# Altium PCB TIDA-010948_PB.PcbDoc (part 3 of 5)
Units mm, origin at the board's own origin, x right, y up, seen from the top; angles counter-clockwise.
Board outline 140 x 180 mm, 4 copper layers (Top Layer, Mid-Layer 1, Mid-Layer 2, Bottom Layer), stack 1.554 mm thick; 481 components, 274 nets, 1278 pads, 301 vias.
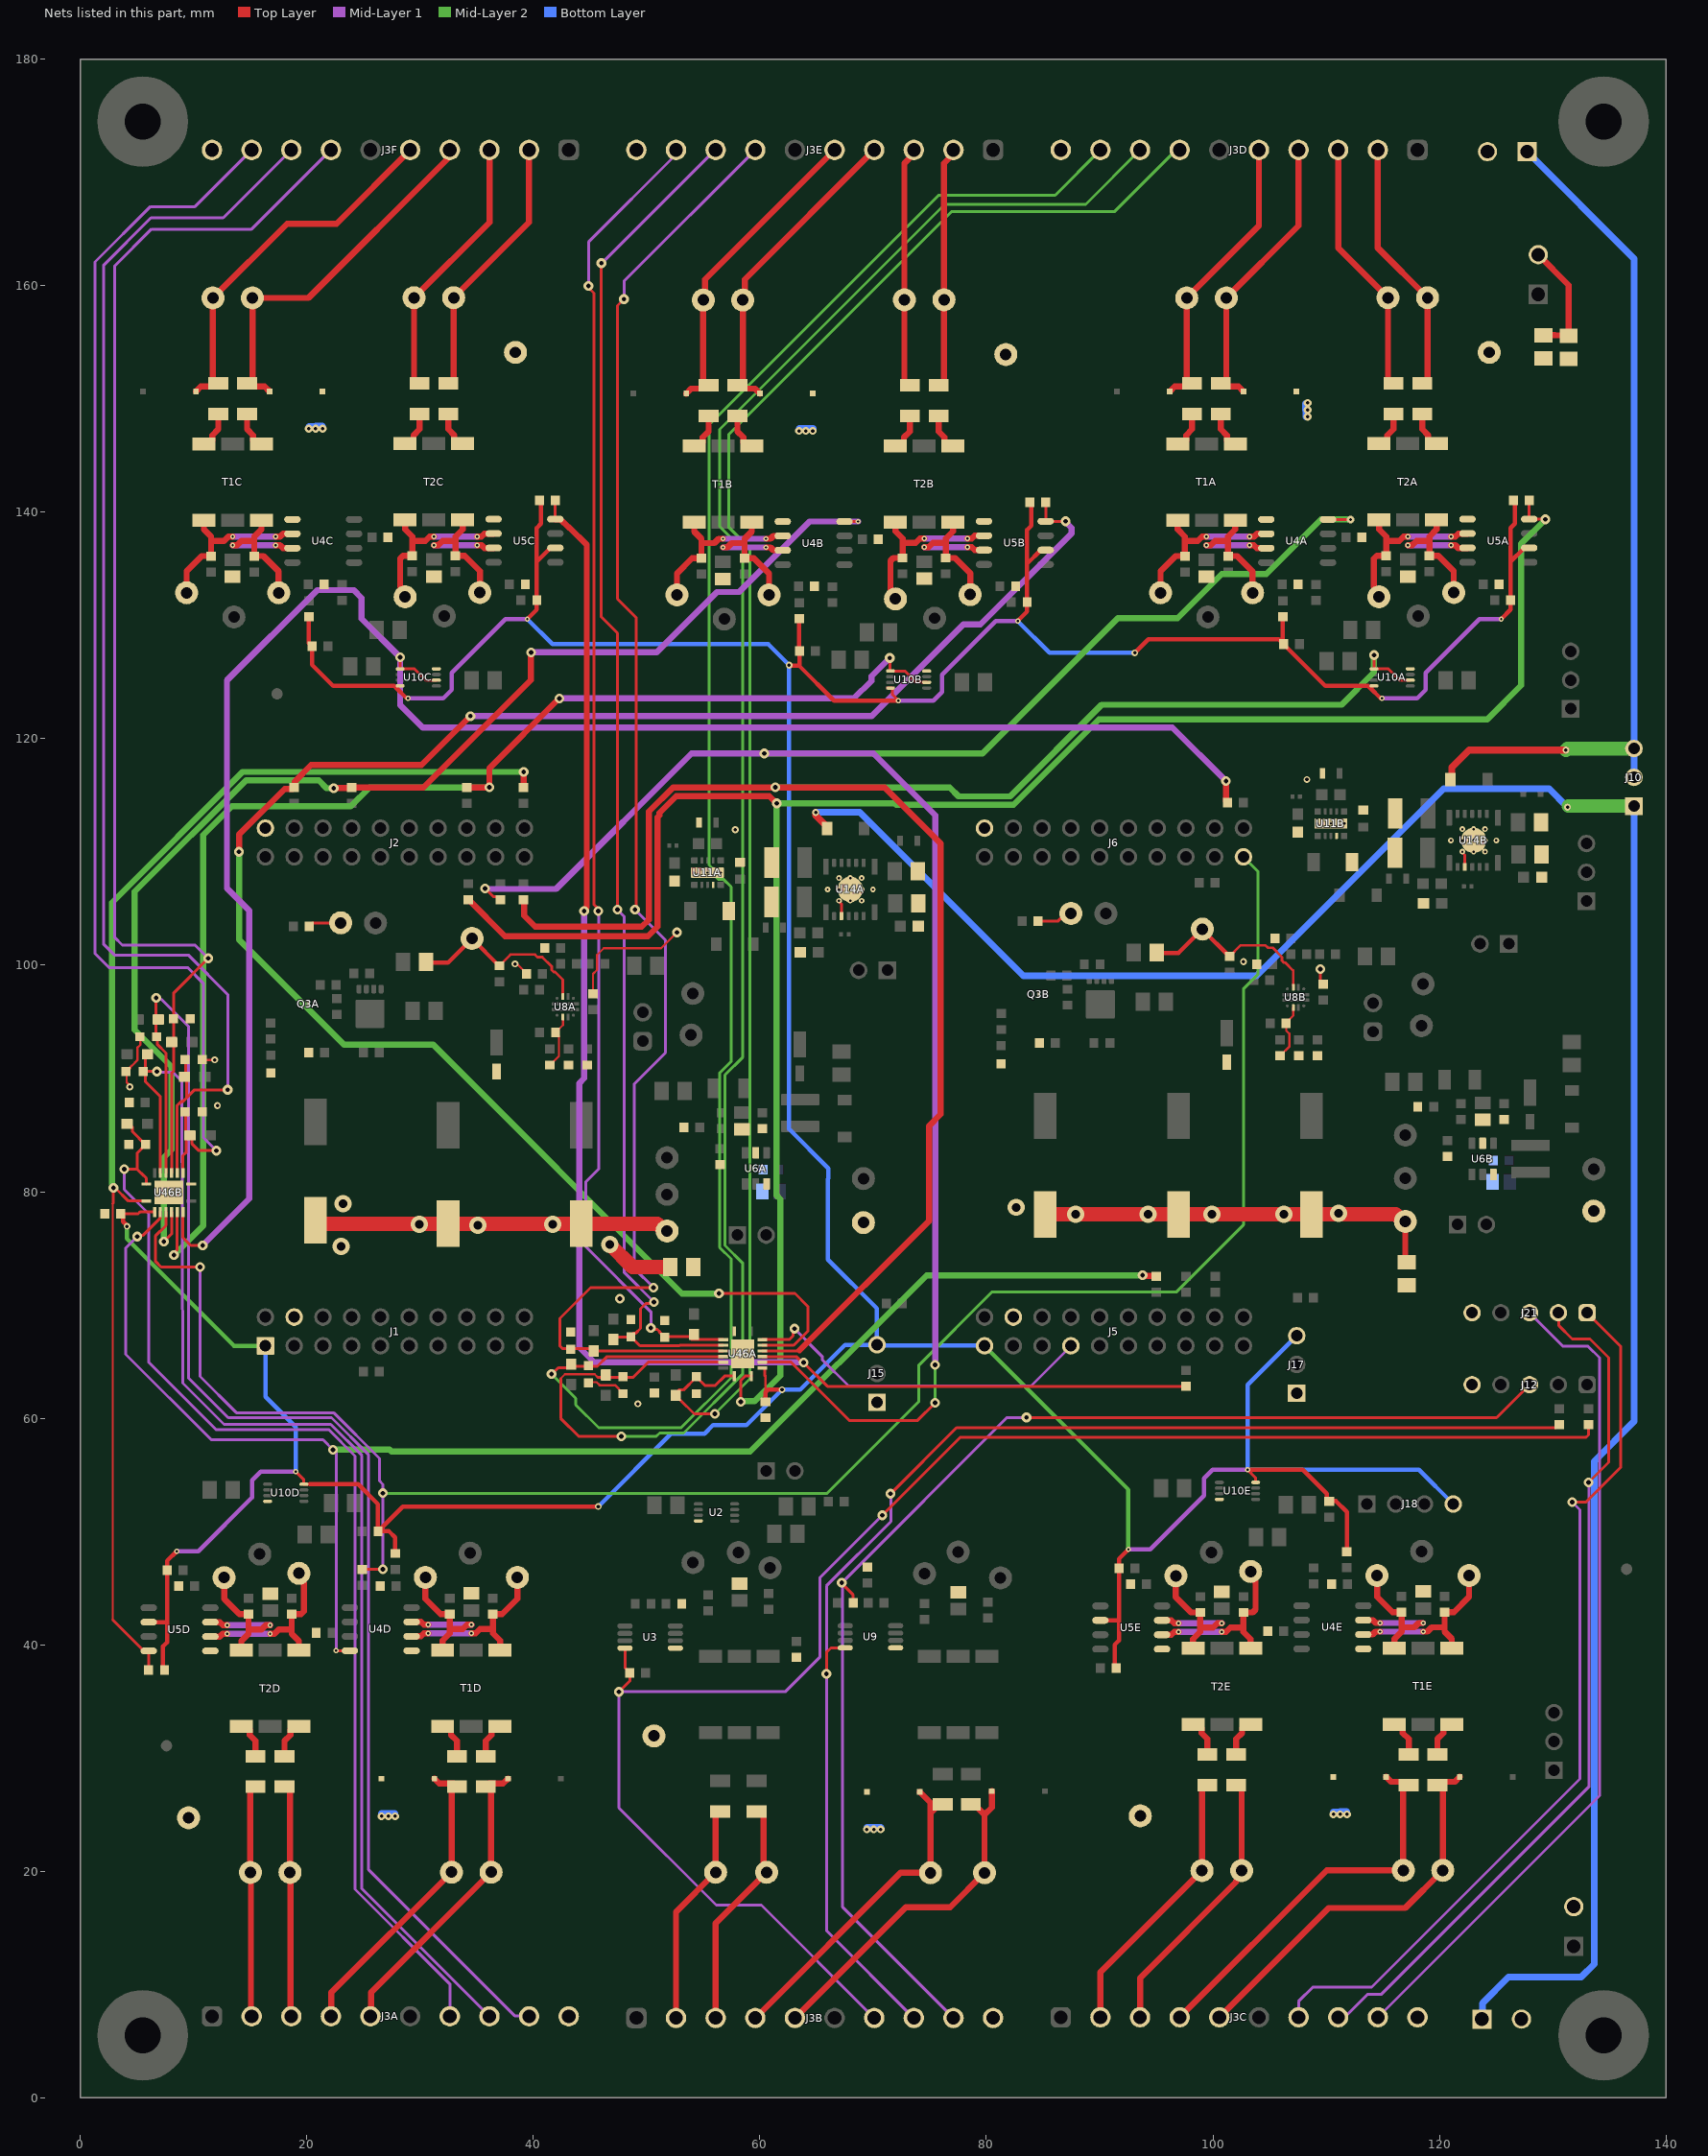
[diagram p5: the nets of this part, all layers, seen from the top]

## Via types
v1: diameter 0.457/0.457/0.457/0.457 (per signal layer), hole 0.203, Top Layer to Bottom Layer, tented both sides, 68 vias
v2: diameter 0.864, hole 0.406, Top Layer to Mid-Layer 1, 51 vias
v3: diameter 0.5, hole 0.2, Top Layer to Bottom Layer, 40 vias
v4: diameter 0.864, hole 0.406, Top Layer to Bottom Layer, 40 vias
v5: diameter 0.7, hole 0.3, Top Layer to Bottom Layer, 36 vias
v6: diameter 0.61, hole 0.3, Top Layer to Bottom Layer, 29 vias
v7: diameter 1.524, hole 0.762, Top Layer to Bottom Layer, tented both sides, 12 vias
v8: diameter 0.203, hole 0.203, Top Layer to Bottom Layer, tented both sides, 8 vias
v9: diameter 1.016, hole 0.508, Top Layer to Bottom Layer, tented both sides, 6 vias
v10: diameter 0.61, hole 0.3, Top Layer to Mid-Layer 1, 3 vias
v11: diameter 0.457, hole 0.203, Top Layer to Mid-Layer 1, tented both sides, 2 vias
v12: diameter 0.5, hole 0.2, Top Layer to Bottom Layer, tented both sides, 2 vias
v13: diameter 0.7, hole 0.203, Top Layer to Mid-Layer 1, tented both sides, 1 vias
v14: diameter 0.7, hole 0.254, Top Layer to Bottom Layer, 1 vias
v15: diameter 0.7, hole 0.254, Top Layer to Mid-Layer 1, 1 vias
v16: diameter 0.457/0.457 (per signal layer), hole 0.203, Top Layer to Mid-Layer 1, tented both sides, 1 vias

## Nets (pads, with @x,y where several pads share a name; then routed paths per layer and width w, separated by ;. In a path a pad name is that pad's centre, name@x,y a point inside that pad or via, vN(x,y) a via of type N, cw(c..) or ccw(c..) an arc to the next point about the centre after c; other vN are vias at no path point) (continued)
24V0_EXTERNAL_1: D6A.2 J10.1 J19.1 | length 204.1
  Top Layer w0.6: v6(64.92,113.497) 64.922,113.495 64.922,113.237 65.935,112.224 D6A.2@65.935,112.072
  Mid-Layer 2 w0.6: v6(131.311,113.96) 131.313,113.96 v6@131.407,114.054
  Mid-Layer 2 w1.2: v6@131.407,114.054 J10.1@137.181,114.054
  Bottom Layer w0.6: v6(64.92,113.497) 66.857,113.497 66.871,113.51 68.805,113.51 83.25,99.065 103.855,99.065 120.371,115.581 129.69,115.581 v6(131.311,113.96) ; J19.1@123.75,6.935 123.805,6.99 123.805,8.333 126.104,10.632 132.519,10.632 133.669,11.783 133.669,56.19 137.181,59.702 J10.1@137.181,114.054
24V0_EXTERNAL_2: D6B.2 J10.2 J10.3 J20.1 | length 77.1
  Top Layer w0.6: D6B.2@120.981,116.399 121.105,116.522 121.105,117.479 122.625,118.999 v6(131.175,118.999)
  Mid-Layer 2 w1.2: v6(131.175,118.999) 131.311,119.134 J10.3@137.181,119.134
  Bottom Layer w0.6: J20.1@127.75,171.85 137.181,162.419 J10.3@137.181,119.134 J10.2@137.181,116.594
BULK_RDYA: NT9A.1 R36A.2 TP34A.1 U8A.3 | length 16.9
  Top Layer w0.229: R36A.2@36.987,99.955 37.973,100.94 40.14,100.94 40.357,100.723 40.781,100.723 41.612,99.892 41.612,99.582 41.789,99.405 41.907,99.405 42.596,98.716 U8A.3@42.596,97.353
  Top Layer w0.381: NT9A.1@30.53,100.294 30.58,100.244 32.461,100.244 TP34A.1@34.58,102.363 34.58,102.337 36.962,99.955 R36A.2@36.987,99.955
BULK_RDYB: NT9B.1 R36B.2 TP34B.1 U8B.3 | length 16.9
  Top Layer w0.229: R36B.2@101.481,100.783 102.466,101.769 104.633,101.769 104.851,101.552 105.274,101.552 106.106,100.72 106.106,100.41 106.282,100.233 106.4,100.233 107.089,99.545 U8B.3@107.089,98.182
  Top Layer w0.381: NT9B.1@95.023,101.123 95.073,101.073 96.955,101.073 TP34B.1@99.074,103.192 99.074,103.165 101.456,100.783 R36B.2@101.481,100.783
CLKA_N: C15D.1 J3A.2 TP26D.1 | length 20.6
  Top Layer w0.54: J3A.2@15.115,7.181 15.058,7.239 15.058,19.83 TP26D.1@15,19.887 15,27.167 15.28,27.448 C15D.1@15.469,27.448
CLKA_P: C14D.1 J3A.3 TP25D.1 | length 20.6
  Top Layer w0.54: C14D.1@18.02,27.448 18.22,27.448 18.5,27.167 TP25D.1@18.5,19.887 18.558,19.83 18.558,7.239 J3A.3@18.615,7.181
CLKB_N: C35.1 J3B.2 TP10.1 | length 19.9
  Top Layer w0.54: J3B.2@52.591,7.032 52.591,16.398 TP10.1@56.091,19.898 56.091,25 56.371,25.28 C35.1@56.488,25.28
CLKB_P: C34.1 J3B.3 TP7.1 | length 20.7
  Top Layer w0.54: J3B.3@56.091,7.032 56.091,15.395 TP7.1@60.594,19.898 60.314,20.177 60.314,25 60.034,25.28 C34.1@59.709,25.28
CLKC_N: C15E.1 J3C.2 TP26E.1 | length 24.5
  Top Layer w0.54: J3C.2@90.067,7.09 90.067,11.074 TP26E.1@99.042,20.05 99.042,27.33 99.322,27.61 C15E.1@99.511,27.61
CLKC_P: C14E.1 J3C.3 TP25E.1 | length 24.6
  Top Layer w0.54: J3C.3@93.567,7.09 93.567,10.567 102.045,19.045 102.045,19.149 102.542,19.646 102.542,27.33 102.262,27.61 C14E.1@102.062,27.61
CLKD_N: C15A.1 J3D.2 TP26A.1 | length 22.7
  Top Layer w0.54: J3D.2@114.567,172 114.567,163.341 TP26A.1@118.958,158.95 118.958,151.67 118.678,151.39 C15A.1@118.489,151.39
CLKD_P: C14A.1 J3D.3 TP25A.1 | length 22.7
  Top Layer w0.54: J3D.3@111.067,172 111.067,163.341 TP25A.1@115.458,158.95 115.458,151.67 115.738,151.39 C14A.1@115.938,151.39
CLKE_N: C15B.1 J3E.2 TP26B.1 | length 21.4
  Top Layer w0.54: C15B.1@75.79,151.203 75.978,151.203 76.258,151.483 TP26B.1@76.258,158.763 76.258,170.826 77.091,171.659 J3E.2@77.091,172
CLKE_P: C14B.1 J3E.3 TP25B.1 | length 21.5
  Top Layer w0.54: C14B.1@73.238,151.203 73.038,151.203 72.758,151.483 TP25B.1@72.758,158.763 72.758,170.826 73.591,171.659 J3E.3@73.591,172
CLKF_N: C15C.1 J3F.2 TP26C.1 | length 23.7
  Top Layer w0.54: C15C.1@32.489,151.39 32.678,151.39 32.958,151.67 TP26C.1@32.958,158.95 39.615,165.608 J3F.2@39.615,172
CLKF_P: C14C.1 J3F.3 TP25C.1 | length 23.7
  Top Layer w0.54: C14C.1@29.938,151.39 29.738,151.39 29.458,151.67 TP25C.1@29.458,158.95 36.115,165.608 J3F.3@36.115,172
DA1A_N: R24A.2 T1A.3 TP17A.1 U4A.7 | length 18.7
  Top Layer w0.54: v1(99.44,137.086) 99.821,137.086 100.202,137.467 101.345,137.467 ; R24A.2@101.344,136.135 102.148,136.135 103.504,134.779 TP17A.1@103.503,132.895 ; v1(103.25,137.086) 103.631,137.086 103.885,136.832 U4A.7@104.716,136.832 ; 101.345,137.467 101.345,137.848 ; 101.345,137.467 101.345,137.848 ; 101.345,137.467 101.345,136.235 101.345,137.467 ; 101.345,137.848 101.98,138.483 ; 101.345,137.848 101.98,138.483 ; 101.98,138.483 T1A.3@101.979,139.308 101.98,138.483
  Mid-Layer 1 w0.54: v1(99.44,137.086) v1(103.25,137.086)
DA1A_P: R22A.2 T1A.1 TP16A.1 U4A.6 | length 15.4
  Top Layer w0.54: TP16A.1@95.375,132.895 95.376,134.792 96.718,136.135 R22A.2@97.534,136.135 ; T1A.1@96.899,139.308 96.9,138.482 97.534,137.848 97.534,137.467 ; R22A.2@97.534,136.235 97.534,137.467 ; v1(99.44,137.848) 99.059,137.848 98.678,137.467 97.534,137.467 ; v1(103.25,137.848) 103.641,137.848 103.895,138.102 U4A.6@104.716,138.102
  Mid-Layer 1 w0.54: v1(99.44,137.848) v1(103.25,137.848)
DA1B_N: R24B.2 T1B.3 TP17B.1 U4B.7 | length 18.7
  Top Layer w0.54: v1(56.74,136.899) 57.121,136.899 57.502,137.28 58.645,137.28 ; R24B.2@58.645,135.948 59.449,135.948 60.804,134.592 TP17B.1@60.804,132.708 ; v1(60.55,136.899) 60.931,136.899 61.185,136.645 U4B.7@62.016,136.645 ; 58.645,137.28 58.645,136.048 58.645,137.28 ; 58.645,137.28 58.645,137.661 ; 58.645,137.28 58.645,137.661 ; 58.645,137.661 59.28,138.296 ; 58.645,137.661 59.28,138.296 ; 59.28,138.296 59.28,139.121 59.28,138.296
  Mid-Layer 1 w0.54: v1(56.74,136.899) v1(60.55,136.899)
DA1B_P: R22B.2 T1B.1 TP16B.1 U4B.6 | length 15.4
  Top Layer w0.54: TP16B.1@52.676,132.708 52.676,134.605 54.018,135.948 R22B.2@54.835,135.948 ; T1B.1@54.2,139.121 54.2,138.295 54.835,137.661 54.835,137.28 ; R22B.2@54.835,136.048 54.835,137.28 ; v1(56.74,137.661) 56.359,137.661 55.978,137.28 54.835,137.28 ; v1(60.55,137.661) 60.941,137.661 61.195,137.915 U4B.6@62.016,137.915
  Mid-Layer 1 w0.54: v1(56.74,137.661) v1(60.55,137.661)
DA1C_N: R24C.2 T1C.3 TP17C.1 U4C.7 | length 18.7
  Top Layer w0.54: v1(13.44,137.086) 13.821,137.086 14.202,137.467 15.345,137.467 ; R24C.2@15.344,136.135 16.148,136.135 17.504,134.779 TP17C.1@17.503,132.895 ; v1(17.25,137.086) 17.631,137.086 17.885,136.832 U4C.7@18.715,136.832 ; 15.345,137.467 15.345,136.235 15.345,137.467 ; 15.345,137.467 15.345,137.848 ; 15.345,137.467 15.345,137.848 ; 15.345,137.848 15.98,138.483 ; 15.345,137.848 15.98,138.483 ; 15.98,138.483 T1C.3@15.979,139.308 15.98,138.483
  Mid-Layer 1 w0.54: v1(13.44,137.086) v1(17.25,137.086)
DA1C_P: R22C.2 T1C.1 TP16C.1 U4C.6 | length 15.4
  Top Layer w0.54: TP16C.1@9.375,132.895 9.376,134.792 10.718,136.135 R22C.2@11.534,136.135 ; T1C.1@10.899,139.308 10.9,138.482 11.534,137.848 11.534,137.467 ; R22C.2@11.534,136.235 11.534,137.467 ; v1(13.44,137.848) 13.059,137.848 12.678,137.467 11.534,137.467 ; v1(17.25,137.848) 17.641,137.848 17.895,138.102 U4C.6@18.715,138.102
  Mid-Layer 1 w0.54: v1(13.44,137.848) v1(17.25,137.848)
DA1D_N: R24D.2 T1D.3 TP17D.1 U4D.7 | length 18.7
  Top Layer w0.54: U4D.7@29.243,42.006 30.073,42.006 30.327,41.752 v1(30.708,41.752) ; TP17D.1@30.455,45.943 30.454,44.058 31.81,42.703 R24D.2@32.614,42.703 ; v1(34.518,41.752) 34.137,41.752 33.756,41.371 32.613,41.371 ; 31.978,40.355 T1D.3@31.979,39.529 31.978,40.355 ; 31.978,40.355 32.613,40.99 ; 31.978,40.355 32.613,40.99 ; 32.613,40.99 32.613,41.371 ; 32.613,40.99 32.613,41.371 ; 32.613,41.371 32.613,42.603 32.613,41.371
  Mid-Layer 1 w0.54: v1(30.708,41.752) v1(34.518,41.752)
DA1D_P: R22D.2 T1D.1 TP16D.1 U4D.6 | length 15.4
  Top Layer w0.54: U4D.6@29.243,40.736 30.063,40.736 30.317,40.99 v1(30.708,40.99) ; v1(34.518,40.99) 34.899,40.99 35.28,41.371 36.424,41.371 ; R22D.2@36.424,42.603 36.424,41.371 ; R22D.2@36.424,42.703 37.24,42.703 38.582,44.045 TP16D.1@38.583,45.943 ; T1D.1@37.059,39.529 37.058,40.355 36.424,40.99 36.424,41.371
  Mid-Layer 1 w0.54: v1(30.708,40.99) v1(34.518,40.99)
DA1E_N: R24E.2 T1E.3 TP17E.1 U4E.7 | length 18.7
  Top Layer w0.54: U4E.7@113.285,42.168 114.115,42.168 114.369,41.914 v1(114.75,41.914) ; TP17E.1@114.496,46.105 114.496,44.221 115.852,42.865 R24E.2@116.655,42.865 ; v1(118.56,41.914) 118.179,41.914 117.798,41.533 116.655,41.533 ; 116.02,40.517 116.02,39.692 116.02,40.517 ; 116.02,40.517 116.655,41.152 ; 116.02,40.517 116.655,41.152 ; 116.655,41.152 116.655,41.533 ; 116.655,41.152 116.655,41.533 ; 116.655,41.533 116.655,42.765 116.655,41.533
  Mid-Layer 1 w0.54: v1(114.75,41.914) v1(118.56,41.914)
DA1E_P: R22E.2 T1E.1 TP16E.1 U4E.6 | length 15.4
  Top Layer w0.54: U4E.6@113.285,40.898 114.105,40.898 114.359,41.152 v1(114.75,41.152) ; v1(118.56,41.152) 118.941,41.152 119.322,41.533 120.466,41.533 ; R22E.2@120.466,42.765 120.466,41.533 ; R22E.2@120.466,42.865 121.282,42.865 122.624,44.208 TP16E.1@122.624,46.105 ; T1E.1@121.1,39.692 121.1,40.518 120.466,41.152 120.466,41.533
  Mid-Layer 1 w0.54: v1(114.75,41.152) v1(118.56,41.152)
DA2A_N: R25A.2 T2A.3 TP19A.1 U5A.7 | length 20
  Top Layer w0.54: v1(117.208,137.106) 117.589,137.106 117.97,137.487 119.113,137.487 ; R25A.2@119.113,136.255 119.113,137.487 ; T2A.3@119.748,139.329 119.748,138.503 119.113,137.868 119.113,137.487 ; v1(121.018,137.106) 121.399,137.106 121.653,136.852 U5A.7@122.484,136.852 ; 119.916,136.155 121.272,134.8 ; 119.916,136.155 121.272,134.8 ; 119.916,136.155 R25A.2@119.113,136.155 119.916,136.155 ; 121.272,134.8 TP19A.1@121.272,132.915 121.272,134.8
  Mid-Layer 1 w0.54: v1(117.208,137.106) v1(121.018,137.106)
DA2A_P: R23A.2 T2A.1 TP18A.1 U5A.6 | length 15.5
  Top Layer w0.54: TP18A.1@114.668,132.535 114.668,132.981 114.227,133.422 114.227,135.896 114.486,136.155 R23A.2@115.302,136.155 ; T2A.1@114.668,139.329 114.668,138.503 115.302,137.868 115.302,137.487 ; R23A.2@115.302,136.255 115.302,137.487 ; v1(117.208,137.868) 116.827,137.868 116.446,137.487 115.302,137.487 ; v1(121.018,137.868) 121.409,137.868 121.663,138.122 U5A.6@122.484,138.122
  Mid-Layer 1 w0.54: v1(117.208,137.868) v1(121.018,137.868)
DA2B_N: R25B.2 T2B.3 TP19B.1 U5B.7 | length 20
  Top Layer w0.54: v1(74.508,136.919) 74.889,136.919 75.27,137.3 76.413,137.3 ; R25B.2@76.413,136.068 76.413,137.3 ; T2B.3@77.048,139.142 77.048,138.316 76.413,137.681 76.413,137.3 ; v1(78.318,136.919) 78.699,136.919 78.953,136.665 U5B.7@79.784,136.665 ; 77.217,135.968 78.572,134.613 ; 77.217,135.968 78.572,134.613 ; 77.217,135.968 R25B.2@76.413,135.968 77.217,135.968 ; 78.572,134.613 TP19B.1@78.572,132.728 78.572,134.613
  Mid-Layer 1 w0.54: v1(74.508,136.919) v1(78.318,136.919)
DA2B_P: R23B.2 T2B.1 TP18B.1 U5B.6 | length 15.5
  Top Layer w0.54: TP18B.1@71.968,132.348 71.968,132.794 71.528,133.235 71.528,135.709 71.787,135.968 R23B.2@72.603,135.968 ; T2B.1@71.968,139.142 71.968,138.316 72.603,137.681 72.603,137.3 ; R23B.2@72.603,136.068 72.603,137.3 ; v1(74.508,137.681) 74.127,137.681 73.746,137.3 72.603,137.3 ; v1(78.318,137.681) 78.709,137.681 78.963,137.935 U5B.6@79.784,137.935
  Mid-Layer 1 w0.54: v1(74.508,137.681) v1(78.318,137.681)
DA2C_N: R25C.2 T2C.3 TP19C.1 U5C.7 | length 20
  Top Layer w0.54: v1(31.208,137.106) 31.589,137.106 31.97,137.487 33.113,137.487 ; R25C.2@33.113,136.255 33.113,137.487 ; T2C.3@33.748,139.329 33.748,138.503 33.113,137.868 33.113,137.487 ; v1(35.018,137.106) 35.399,137.106 35.653,136.852 U5C.7@36.484,136.852 ; 33.916,136.155 35.272,134.8 ; 33.916,136.155 R25C.2@33.113,136.155 33.916,136.155 ; 33.916,136.155 35.272,134.8 ; 35.272,134.8 TP19C.1@35.272,132.915 35.272,134.8
  Mid-Layer 1 w0.54: v1(31.208,137.106) v1(35.018,137.106)
DA2C_P: R23C.2 T2C.1 TP18C.1 U5C.6 | length 15.5
  Top Layer w0.54: TP18C.1@28.668,132.535 28.668,132.981 28.227,133.422 28.227,135.896 28.486,136.155 R23C.2@29.302,136.155 ; T2C.1@28.668,139.329 28.668,138.503 29.302,137.868 29.302,137.487 ; R23C.2@29.302,136.255 29.302,137.487 ; v1(31.208,137.868) 30.827,137.868 30.446,137.487 29.302,137.487 ; v1(35.018,137.868) 35.409,137.868 35.663,138.122 U5C.6@36.484,138.122
  Mid-Layer 1 w0.54: v1(31.208,137.868) v1(35.018,137.868)
DA2D_N: R25D.2 T2D.3 TP19D.1 U5D.7 | length 20
  Top Layer w0.54: U5D.7@11.474,41.985 12.305,41.985 12.559,41.731 v1(12.94,41.731) ; T2D.3@14.21,39.509 14.21,40.334 14.845,40.969 14.845,41.35 ; R25D.2@14.845,42.582 14.845,41.35 ; v1(16.75,41.731) 16.369,41.731 15.988,41.35 14.845,41.35 ; 12.686,44.038 TP19D.1@12.686,45.922 12.686,44.038 ; 12.686,44.038 14.042,42.682 ; 12.686,44.038 14.042,42.682 ; 14.042,42.682 R25D.2@14.845,42.682 14.042,42.682
  Mid-Layer 1 w0.54: v1(12.94,41.731) v1(16.75,41.731)
DA2D_P: R23D.2 T2D.1 TP18D.1 U5D.6 | length 15.5
  Top Layer w0.54: U5D.6@11.474,40.715 12.295,40.715 12.549,40.969 v1(12.94,40.969) ; v1(16.75,40.969) 17.131,40.969 17.512,41.35 18.656,41.35 ; R23D.2@18.656,42.582 18.656,41.35 ; R23D.2@18.656,42.682 19.472,42.682 19.731,42.941 19.731,45.415 19.29,45.856 TP18D.1@19.29,46.303 ; T2D.1@19.29,39.509 19.29,40.335 18.656,40.969 18.656,41.35
  Mid-Layer 1 w0.54: v1(12.94,40.969) v1(16.75,40.969)
DA2E_N: R25E.2 T2E.3 TP19E.1 U5E.7 | length 20
  Top Layer w0.54: U5E.7@95.516,42.148 96.347,42.148 96.601,41.894 v1(96.982,41.894) ; T2E.3@98.252,39.671 98.252,40.497 98.887,41.132 98.887,41.513 ; R25E.2@98.887,42.745 98.887,41.513 ; v1(100.792,41.894) 100.411,41.894 100.03,41.513 98.887,41.513 ; 96.728,44.2 TP19E.1@96.728,46.085 96.728,44.2 ; 96.728,44.2 98.084,42.845 ; 96.728,44.2 98.084,42.845 ; 98.084,42.845 R25E.2@98.887,42.845 98.084,42.845
  Mid-Layer 1 w0.54: v1(96.982,41.894) v1(100.792,41.894)
DA2E_P: R23E.2 T2E.1 TP18E.1 U5E.6 | length 15.5
  Top Layer w0.54: U5E.6@95.516,40.878 96.337,40.878 96.591,41.132 v1(96.982,41.132) ; v1(100.792,41.132) 101.173,41.132 101.554,41.513 102.698,41.513 ; R23E.2@102.698,42.745 102.698,41.513 ; R23E.2@102.698,42.845 103.514,42.845 103.773,43.104 103.773,45.578 103.332,46.019 TP18E.1@103.332,46.465 ; T2E.1@103.332,39.671 103.332,40.497 102.698,41.132 102.698,41.513
  Mid-Layer 1 w0.54: v1(96.982,41.132) v1(100.792,41.132)
DATAA_N: C13D.1 J3A.4 L2D.2 TP24D.1 | length 27.3
  Top Layer w0.54: J3A.4@22.115,7.181 22.156,7.222 22.156,9.295 TP24D.1@32.769,19.908 32.769,27.167 33.049,27.448 C13D.1@33.249,27.448 32.969,27.728 31.691,27.728 L2D.2@31.256,28.163
DATAA_P: C12D.1 J3A.5 L1D.1 TP23D.1 | length 27.3
  Top Layer w0.54: J3A.5@25.615,7.181 25.651,7.217 25.651,9.295 TP23D.1@36.264,19.908 36.264,27.167 35.984,27.448 C12D.1@35.789,27.448 36.069,27.728 37.322,27.728 L1D.1@37.757,28.163
DATAB_N: C23.1 J3B.4 L4.2 TP4.1 | length 29.7
  Top Layer w0.54: J3B.4@59.591,7.032 72.414,19.854 TP4.1@75.065,19.854 75.065,25.132 ; L4.2@74.125,26.983 75.065,26.043 75.065,25.132 ; C23.1@76.14,25.882 75.815,25.882 75.065,25.132
DATAB_P: C21.1 J3B.5 L3.1 TP1.1 | length 31.1
  Top Layer w0.54: J3B.5@63.091,7.032 72.879,16.82 76.801,16.82 TP1.1@79.836,19.854 79.836,24.988 ; C21.1@78.617,25.882 78.942,25.882 79.836,24.988 ; L3.1@80.482,27.063 80.482,25.634 79.836,24.988
DATAC_N: C13E.1 J3C.4 L2E.2 TP24E.1 | length 35.3
  Top Layer w0.54: J3C.4@97.067,7.09 110.047,20.07 TP24E.1@116.811,20.07 116.811,27.33 117.091,27.61 C13E.1@117.291,27.61 117.011,27.89 115.733,27.89 L2E.2@115.298,28.325
DATAC_P: C12E.1 J3C.5 L1E.1 TP23E.1 | length 35.2
  Top Layer w0.54: J3C.5@100.567,7.09 110.227,16.75 116.986,16.75 TP23E.1@120.306,20.07 120.306,27.33 120.026,27.61 C12E.1@119.831,27.61 120.111,27.89 121.364,27.89 L1E.1@121.799,28.325
DATAD_N: C13A.1 J3D.4 L2A.2 TP24A.1 | length 25.9
  Top Layer w0.54: L2A.2@102.702,150.675 102.267,151.11 100.989,151.11 C13A.1@100.709,151.39 100.909,151.39 101.189,151.67 TP24A.1@101.189,158.93 107.567,165.308 J3D.4@107.567,172
DATAD_P: C12A.1 J3D.5 L1A.1 TP23A.1 | length 25.8
  Top Layer w0.54: L1A.1@96.201,150.675 96.636,151.11 97.889,151.11 C12A.1@98.169,151.39 97.974,151.39 97.694,151.67 TP23A.1@97.694,158.93 104.067,165.303 J3D.5@104.067,172
DATAE_N: C13B.1 J3E.4 L2B.2 TP24B.1 | length 28.2
  Top Layer w0.54: L2B.2@60.003,150.488 59.568,150.923 58.29,150.923 C13B.1@58.01,151.203 58.209,151.203 58.489,151.483 TP24B.1@58.489,158.743 58.659,158.912 58.659,160.568 J3E.4@70.091,172
DATAE_P: C12B.1 J3E.5 L1B.1 TP23B.1 | length 28.2
  Top Layer w0.54: L1B.1@53.502,150.488 53.936,150.923 55.189,150.923 C12B.1@55.47,151.203 55.275,151.203 54.994,151.483 TP23B.1@54.994,158.743 55.159,158.907 55.159,160.568 J3E.5@66.591,172
DATAF_N: C13C.1 J3F.4 L2C.2 TP24C.1 | length 33.3
  Top Layer w0.54: L2C.2@16.702,150.675 16.267,151.11 14.989,151.11 C13C.1@14.709,151.39 14.909,151.39 15.189,151.67 TP24C.1@15.189,158.93 20.138,158.93 32.374,171.166 32.374,171.759 J3F.4@32.615,172
DATAF_P: C12C.1 J3F.5 L1C.1 TP23C.1 | length 33
  Top Layer w0.54: L1C.1@10.201,150.675 10.636,151.11 11.889,151.11 C12C.1@12.169,151.39 11.974,151.39 11.694,151.67 TP23C.1@11.694,158.93 18.251,165.487 22.602,165.487 J3F.5@29.115,172
DB1A_N: C13A.2 T1A.4 | length 3.4
  Top Layer w0.54: C13A.2@100.709,148.69 100.709,147.33 101.233,146.806 101.233,146.341 101.535,146.039 T1A.4@101.979,146.039
DB1A_P: C12A.2 T1A.6 | length 3.4
  Top Layer w0.54: T1A.6@96.899,146.039 97.344,146.039 97.645,146.341 97.645,146.806 98.169,147.33 C12A.2@98.169,148.69
DB1B_N: C13B.2 T1B.4 | length 3.4
  Top Layer w0.54: C13B.2@58.01,148.503 58.01,147.143 58.533,146.619 58.533,146.154 58.835,145.852 T1B.4@59.28,145.852
DB1B_P: C12B.2 T1B.6 | length 3.4
  Top Layer w0.54: T1B.6@54.2,145.852 54.644,145.852 54.946,146.154 54.946,146.62 55.47,147.143 C12B.2@55.47,148.503
DB1C_N: C13C.2 T1C.4 | length 3.4
  Top Layer w0.54: C13C.2@14.709,148.69 14.709,147.33 15.233,146.806 15.233,146.341 15.535,146.039 T1C.4@15.979,146.039
DB1C_P: C12C.2 T1C.6 | length 3.4
  Top Layer w0.54: T1C.6@10.899,146.039 11.344,146.039 11.645,146.341 11.645,146.807 12.169,147.33 C12C.2@12.169,148.69
DB1D_N: C13D.2 T1D.4 | length 3.4
  Top Layer w0.54: T1D.4@31.979,32.798 32.423,32.798 32.725,32.496 32.725,32.031 33.249,31.507 C13D.2@33.249,30.148
DB1D_P: C12D.2 T1D.6 | length 3.4
  Top Layer w0.54: C12D.2@35.789,30.148 35.789,31.507 36.313,32.031 36.313,32.496 36.614,32.798 T1D.6@37.059,32.798
DB1E_N: C13E.2 T1E.4 | length 3.4
  Top Layer w0.54: T1E.4@116.021,32.961 116.465,32.961 116.767,32.659 116.767,32.194 117.291,31.67 C13E.2@117.291,30.31
DB1E_P: C12E.2 T1E.6 | length 3.4
  Top Layer w0.54: C12E.2@119.831,30.31 119.831,31.67 120.355,32.194 120.355,32.659 120.656,32.961 T1E.6@121.101,32.961
DB2A_N: C15A.2 T2A.4 | length 3.4
  Top Layer w0.54: C15A.2@118.489,148.69 118.489,147.33 119.002,146.818 119.002,146.361 119.303,146.06 T2A.4@119.748,146.06
DB2A_P: C14A.2 T2A.6 | length 3.4
  Top Layer w0.54: T2A.6@114.668,146.06 115.112,146.06 115.414,146.361 115.414,146.806 115.938,147.33 C14A.2@115.938,148.69
DB2B_N: C15B.2 T2B.4 | length 3.4
  Top Layer w0.54: C15B.2@75.79,148.503 75.79,147.143 76.302,146.631 76.302,146.174 76.604,145.873 T2B.4@77.048,145.873
DB2B_P: C14B.2 T2B.6 | length 3.4
  Top Layer w0.54: T2B.6@71.968,145.873 72.413,145.873 72.715,146.174 72.715,146.62 73.238,147.143 C14B.2@73.238,148.503
DB2C_N: C15C.2 T2C.4 | length 3.4
  Top Layer w0.54: C15C.2@32.489,148.69 32.489,147.33 33.002,146.818 33.002,146.361 33.303,146.06 T2C.4@33.748,146.06
DB2C_P: C14C.2 T2C.6 | length 3.4
  Top Layer w0.54: T2C.6@28.668,146.06 29.112,146.06 29.414,146.361 29.414,146.807 29.938,147.33 C14C.2@29.938,148.69
DB2D_N: C15D.2 T2D.4 | length 3.4
  Top Layer w0.54: T2D.4@14.21,32.778 14.655,32.778 14.956,32.476 14.956,32.02 15.469,31.507 C15D.2@15.469,30.148
DB2D_P: C14D.2 T2D.6 | length 3.4
  Top Layer w0.54: C14D.2@18.02,30.148 18.02,31.507 18.544,32.031 18.544,32.476 18.846,32.778 T2D.6@19.29,32.778
DB2E_N: C15E.2 T2E.4 | length 3.4
  Top Layer w0.54: T2E.4@98.252,32.94 98.697,32.94 98.998,32.639 98.998,32.182 99.511,31.67 C15E.2@99.511,30.31
DB2E_P: C14E.2 T2E.6 | length 3.4
  Top Layer w0.54: C14E.2@102.062,30.31 102.062,31.67 102.586,32.194 102.586,32.639 102.888,32.94 T2E.6@103.332,32.94
"eQEP0_A / PRU1_PERIF0_CLK": R9D.1 R57.2 U5D.4 U46B.1 | length 115.3
  Top Layer w0.2: 2.846,42.199 2.85,76.123 2.85,78.608 2.846,78.612 2.846,78.944
  Top Layer w0.254: 2.846,42.199 5.599,39.445 U5D.4@6.024,39.445 R9D.1@6.024,37.775 ; 2.846,78.944 2.909,79.008 v4(2.909,80.348) 3.069,80.348 4.235,79.181 U46B.1@5.821,79.181
  Top Layer w0.54: R57.2@39.135,115.69 v4@39.135,117.072
  Mid-Layer 2 w0.54: v4(2.909,80.348) 2.847,80.41 2.847,80.639 2.789,80.697 2.789,105.538 14.323,117.073 v4(39.135,117.073)
"eQEP0_B / PRU1_PERIF0_OUT": R58.2 U4D.4 U46B.3 | length 133.8
  Top Layer w0.254: v2(5.02,76.046) 5.136,76.163 5.537,76.163 7.033,77.659 7.033,78.193 U46B.3@7.046,78.206 ; v1(22.581,39.466) U4D.4@23.793,39.466
  Top Layer w0.54: v4(93.799,72.623) 93.855,72.567 94.954,72.567 R58.2@95.01,72.511
  Mid-Layer 1 w0.254: v2(5.02,76.046) 4,75.026 4,65.647 11.555,58.092 21.421,58.092 v4@22.304,57.21 ; v1(22.581,39.466) v4@22.581,56.933
  Mid-Layer 2 w0.54: v4(22.308,57.214) 27.302,57.214 27.464,57.052 59.143,57.052 74.714,72.623 v4(93.799,72.623)
"eQEP0_I / PRU1_PERIF0_IN": J6.71 R17D.1 U46B.4 | length 170.5
  Top Layer w0.254: U46B.4@7.546,78.206 7.546,77.016 6.608,76.077 6.608,73.869 7.118,73.359 v2(10.562,73.359) ; R17D.1@24.864,46.622 24.898,46.656 v2(26.712,46.656)
  Mid-Layer 1 w0.254: v2(10.562,73.359) 10.562,63.698 13.769,60.491 22.354,60.491 26.407,56.438 26.407,54.466 26.712,54.161 v4(26.712,53.382) v2(26.712,46.656)
  Mid-Layer 2 w0.254: v4(26.712,53.382) 26.736,53.357 65.92,53.357 74.047,61.485 74.047,64.696 80.519,71.167 96.804,71.167 102.697,77.06 102.697,97.907 104.001,99.211 104.001,108.262 J6.71@102.697,109.567
"eQEP1_A / PRU1_PERIF1_CLK": J3B.7 R33.1 R64.2 U3.4 | length 144.9
  Top Layer w0.254: v2(47.557,35.837) 48.512,36.793 R33.1@48.512,37.525 48.512,37.55 48.082,37.98 U3.4@48.082,39.693 ; v2(70.803,51.418) 77.706,58.321 132.959,58.321 133.163,58.525 R64.2@133.163,59.421
  Mid-Layer 1 w0.254: J3B.7@70.091,7.032 60.123,17 56.145,17 47.557,25.589 v2(47.557,35.837) 62.235,35.837 65.285,38.887 65.285,45.9 v2(70.803,51.418)
"eQEP1_B / PRU1_PERIF1_OUT": J3B.8 R65.2 U9.4 | length 117.1
  Top Layer w0.254: v2(65.876,37.413) 65.876,39.33 66.266,39.72 U9.4@67.528,39.72 ; v2(71.539,53.331) 77.357,59.148 130.298,59.148 R65.2@130.571,59.421
  Mid-Layer 1 w0.254: v2(71.539,53.331) 71.562,53.308 71.562,50.875 65.876,45.19 v2(65.876,37.413) 65.876,14.746 J3B.8@73.591,7.032
"eQEP1_I / PRU1_PERIF1_IN": J3B.9 J12.3 R19.1 | length 112.7
  Top Layer w0.254: v2(67.222,45.462) 67.222,45.409 68.243,44.388 R19.1@68.243,43.697 ; v2(83.531,60.065) 83.559,60.037 125.049,60.037 J12.3@127.97,62.958
  Mid-Layer 1 w0.254: J3B.9@77.091,7.032 67.303,16.82 67.303,45.38 v2(67.222,45.462) 81.824,60.065 v2(83.531,60.065)
eQEP2_A: J3C.7 J21.1 | length 79.5
  Top Layer w0.254: v2(131.726,52.595) 132.946,52.595 136,55.648 136,66.358 J21.1@133.05,69.308
  Mid-Layer 1 w0.254: J3C.7@107.567,7.09 107.567,8.502 108.823,9.759 114.03,9.759 132.407,28.136 132.407,51.914 v2(131.726,52.595)
eQEP2_B: J3C.8 J21.2 | length 75.9
  Top Layer w0.254: J21.2@130.51,69.308 130.564,69.253 130.564,68.162 131.726,67 133.29,67 134.949,65.341 134.949,56.115 v2(133.163,54.328)
  Mid-Layer 1 w0.254: J3C.8@111.067,7.09 111.363,7.386 111.936,7.386 113.65,9.1 114.857,9.1 133.196,27.439 133.196,54.296 v2(133.163,54.328)
eQEP2_I: J3C.9 J21.3 | length 74.2
  Mid-Layer 1 w0.254: J3C.9@114.567,7.09 134.142,26.665 134.142,65.341 133.134,66.349 130.929,66.349 J21.3@127.97,69.308
"eQEP3_A / PRU0_PERIF0_CLK": R9A.1 R53.1 U5A.4 U46A.1 | length 186.7
  Top Layer w0.254: v4(58.3,61.447) 58.3,63.322 58.693,63.715 U46A.1@59.238,63.715 ; R9A.1@127.934,141.062 U5A.4@127.934,139.392 127.944,139.382 129.361,139.382 v4(129.372,139.372)
  Top Layer w0.54: R53.1@34.242,105.799 34.267,105.799 37.498,102.568 50.119,102.568 50.966,103.415 50.966,113.074 51.127,113.234 51.127,113.454 52.602,114.929 60.842,114.929 v4(61.481,114.29)
  Mid-Layer 2 w0.54: v4(58.3,61.447) 58.362,61.509 59.538,61.509 61.794,63.765 61.794,79.351 61.481,79.664 v4(61.481,114.29) 71.927,114.29 72.04,114.177 82.398,114.177 89.933,121.712 124.229,121.712 127.234,124.717 127.234,137.234 v4(129.372,139.372)
"eQEP3_B / PRU0_PERIF0_OUT": R55.1 U4A.4 U46A.3 | length 181
  Top Layer w0.254: v2(35.735,106.788) 36.451,106.072 36.821,106.072 R55.1@37.094,105.799 ; U46A.3@60.213,64.94 62.762,64.94 67.93,59.772 73.887,59.772 75.459,61.344 v4(75.459,61.361) ; U4A.4@110.165,139.372 110.176,139.361 112.139,139.361 v14(112.15,139.349)
  Mid-Layer 1 w0.54: v2(35.735,106.788) 35.794,106.73 42,106.73 53.971,118.701 v4(60.381,118.701) 70.019,118.701 75.478,113.242 v4(75.478,64.698)
  Mid-Layer 2 w0.254: v4(75.459,61.361) 75.469,61.371 75.469,64.688 v4(75.478,64.698)
  Mid-Layer 2 w0.54: v4(60.381,118.701) 79.658,118.701 91.608,130.651 96.899,130.651 100.791,134.544 104.726,134.544 109.554,139.372 112.128,139.372 v14(112.15,139.349)
"eQEP3_I / PRU0_PERIF2_CLK": R9C.1 R59.1 U5C.4 U46A.4 | length 135.4
  Top Layer w0.254: U5C.4@41.934,139.392 R9C.1@41.934,141.062 ; U46A.4@60.213,65.44 63.21,65.44 63.722,64.928 v2(63.847,64.928) 65.959,62.816 R59.1@97.617,62.816
  Top Layer w0.54: U5C.4@41.934,139.392 42.375,139.392 43.114,138.653 43.178,138.653 44.709,137.121 44.709,105.121 44.472,104.884 v2(44.472,104.796)
  Mid-Layer 1 w0.54: v2(44.472,104.796) 44.472,90.008 44.043,89.579 44.043,66.254 45.369,64.928 v2(63.847,64.928)
"eQEP4_A / PRU0_PERIF0_OUT_EN": R56.1 U10A.2 U10A.5 U46A.5 | length 168.7
  Top Layer w0.254: U46A.5@60.213,65.94 63.456,65.94 63.505,65.989 ; v4(114.227,127.389) U10A.5@114.227,126.172 115.498,126.172 116.498,125.172 U10A.2@117.427,125.172
  Top Layer w0.54: R56.1@39.135,105.799 39.166,105.768 39.166,104.396 40.165,103.397 49.574,103.397 50.193,104.016 50.193,113.566 52.335,115.708 v4(61.366,115.708) 71.015,115.708 75.964,110.759 75.964,86.834 74.932,85.802 74.932,77.416 63.505,65.989
  Mid-Layer 2 w0.54: v4(61.366,115.708) 76.746,115.708 77.538,114.917 82.091,114.917 90.175,123 111.36,123 114.227,125.867 v4(114.227,127.389)
"eQEP4_B / PRU0_PERIF1_CLK": R9B.1 R14.2 U5B.4 U46A.6 | length 169
  Top Layer w0.254: v4(56.378,71.01) 63.1,71.01 64.224,69.885 64.224,67.68 62.985,66.44 U46A.6@60.213,66.44 ; R9B.1@85.234,140.875 U5B.4@85.234,139.205 v2(87,139.205)
  Top Layer w0.54: v4(13.999,110.023) 13.999,111.529 18.029,115.56 18.726,115.56 18.857,115.69 R14.2@18.882,115.69 ; R14.2@18.907,115.811 18.907,116.216 20.374,117.682 30.124,117.682 v2(34.442,122)
  Mid-Layer 1 w0.54: v2(34.442,122) 69.873,122 77.97,130.096 79.477,130.096 87.511,138.131 87.511,138.606 87,139.117 v2(87,139.205)
  Mid-Layer 2 w0.54: v4(13.999,110.023) 13.999,102.267 23.273,92.994 31.149,92.994 53.134,71.01 v4(56.378,71.01)
eQEP4_I: J5.44 U46A.7 | length 31.7
  Top Layer w0.254: U46A.7@60.213,66.94 62.592,66.94 62.928,67.276 62.928,67.791 v2(63.045,67.908)
  Mid-Layer 1 w0.254: v2(63.045,67.908) 65.5,65.453 65.5,65.182 67.838,62.844 83.943,62.844 87.457,66.357 J5.44@87.457,66.387
"eQEP5_A / PRU0_PERIF1_OUT": R32.2 U4B.4 U46B.5 | length 116.1
  Top Layer w0.254: v4(7.367,75.587) 8.046,76.266 U46B.5@8.046,78.206 ; U4B.4@67.466,139.185 v1(68.678,139.185)
  Top Layer w0.54: v4(22.364,115.637) 22.39,115.664 23.931,115.664 R32.2@23.957,115.69 30.278,115.69 39.785,125.197 v2(39.785,127.633)
  Mid-Layer 1 w0.54: v2(39.785,127.633) 50.892,127.633 56.224,132.965 58.168,132.965 64.388,139.185 v1(68.678,139.185)
  Mid-Layer 2 w0.54: v4(7.367,75.587) 7.367,83.018 8.046,83.697 8.046,91.041 4.786,94.3 4.786,106.49 14.629,116.333 21.035,116.333 21.73,115.637 v4(22.364,115.637)
"eQEP5_B / PRU0_PERIF1_OUT_EN": R54.2 U10B.2 U10B.5 U46B.6 | length 117.2
  Top Layer w0.254: v4(8.245,74.399) 8.245,74.563 8.546,74.865 U46B.6@8.546,78.206 ; v2(71.469,127.141) 71.499,127.111 71.499,126.006 71.52,125.985 72.799,125.985 73.799,124.985 U10B.2@74.728,124.985
  Top Layer w0.54: R54.2@34.117,115.69 34.126,115.699 36.101,115.699 v4(36.111,115.708) 36.111,117.388 v2(42.284,123.562)
  Mid-Layer 1 w0.54: v2(42.284,123.562) 68.299,123.562 69.853,125.116 69.853,125.525 v2(71.469,127.141)
  Mid-Layer 2 w0.54: v4(8.245,74.399) 10.845,76.999 10.845,111.503 13.383,114.041 23.869,114.041 25.537,115.708 v4(36.111,115.708)
"eQEP5_I / PRU0_PERIF2_OUT_EN": R63.2 U10C.2 U10C.5 U46B.7 | length 165.3
  Top Layer w0.254: U46B.7@9.046,78.206 9.046,75.962 9.744,75.264 v2(10.787,75.264) ; v2(28.227,127.197) U10C.5@28.227,126.172 29.498,126.172 30.498,125.172 U10C.2@31.427,125.172
  Top Layer w0.54: v2(101.156,116.272) 101.156,115.031 101.17,115.017 101.17,114.483 R63.2@101.3,114.353
  Mid-Layer 1 w0.54: v2(10.787,75.264) 14.902,79.379 14.902,104.834 12.939,106.796 12.939,125.16 20.911,133.132 24.132,133.132 24.824,132.44 24.824,130.6 v2(28.227,127.197) 28.227,122.995 30.222,121 96.428,121 v2(101.156,116.272)
eQEP_AA: C3B.1 J3A.7 R1B.1 U46B.16 | length 100.2
  Top Layer w0.254: v2(3.877,82) 5,82 ; R1B.1@4.32,85.986 4.593,85.713 4.593,85.309 5.72,84.182 5.72,84.157 5.72,84.132 5.004,83.416 5.004,83.13 5,82 ; U46B.16@5.821,80.681 5.821,81.202 5.422,81.601 5.399,81.601 5,82
  Mid-Layer 1 w0.254: v2(3.877,82) 3.877,80.201 6.019,78.058 6.019,64.939 11.958,59 21.918,59 24.255,56.663 24.255,18.403 32.615,10.043 J3A.7@32.615,7.181
eQEP_AD: C3A.1 J3D.7 R1A.1 U46A.16 | length 149.4
  Top Layer w0.254: R1A.1@52.564,62.014 52.564,61.964 52.887,61.641 52.937,61.641 54.201,60.378 v4(56.02,60.378) ; R1A.1@52.589,62.214 52.564,62.214 52.837,62.487 53.241,62.487 54.368,63.614 54.393,63.614 54.418,63.614 55.134,62.899 55.42,62.899 56.073,62.899 56.89,63.715 U46A.16@57.738,63.715
  Mid-Layer 2 w0.254: v4(56.02,60.378) 59.111,63.469 59.111,136.81 57.23,138.692 57.23,146.866 76.91,166.546 91.296,166.546 96.75,172 J3D.7@97.067,172
eQEP_AE: C6A.1 J3E.7 R4A.1 U46A.12 | length 135.5
  Top Layer w0.254: R4A.1@45.335,66.143 43.285,66.143 42.566,66.143 42.334,66.375 42.334,68.807 45.049,71.522 v2(50.609,71.522) ; R4A.1@45.338,65.94 U46A.12@56.763,65.94 ; v2(48,158.828) 47.419,158.247 47.419,132.356 49.054,130.72 49.054,104.996 v2(48.964,104.906)
  Mid-Layer 1 w0.254: v2(48,158.828) 48,160.409 J3E.7@59.591,172 ; v2(48.964,104.906) 51.658,102.212 51.658,92.267 48.921,89.531 48.921,73.21 v2(50.609,71.522)
eQEP_AF: C6B.1 J3F.7 R4B.1 U46B.12 | length 112
  Top Layer w0.254: U46B.12@8.046,81.656 8.046,90.463 8.249,90.666 R4B.1@8.249,93.211 ; R4B.1@8.249,93.215 8.249,95.265 8.249,97.568 v2(11.287,100.605)
  Mid-Layer 1 w0.254: v2(11.287,100.605) 10.117,101.775 3.699,101.775 3,102.474 3,161.728 6.272,165 15.115,165 J3F.7@22.115,172
eQEP_BA: C4B.1 J3A.8 R2B.1 U46B.14 | length 114.5
  Top Layer w0.254: C4B.1@5.534,90.6 C4B.1@5.484,90.6 ; C4B.1@5.72,90.617 v2(6.739,90.617) ; R2B.1@5.92,92.155 5.72,92.155 5.72,90.836 C4B.1@5.484,90.6 ; U46B.14@7.046,81.656 7.046,88.419 5.72,89.745 5.72,90.6 C4B.1@5.484,90.6
  Mid-Layer 1 w0.254: v2(6.739,90.617) 6.813,90.543 8.148,90.565 8.949,89.763 8.949,89 9.046,63.094 12.686,59.454 22.106,59.454 24.851,56.71 24.851,18.45 36.115,7.185 J3A.8@36.115,7.181
eQEP_BD: C4A.1 J3D.8 R2A.1 U46A.14 | length 170.6
  Top Layer w0.2: 42.402,63.494 42.786,63.878 45.415,63.878 45.679,63.614
  Top Layer w0.254: 42.402,63.494 42.402,59.989 44.001,58.39 v4(47.765,58.39) ; 45.679,63.614 46.395,63.614 47.926,63.614 48.805,63.614 50.131,64.94 U46A.14@56.763,64.94
  Mid-Layer 2 w0.254: v4(47.765,58.39) 50.837,58.39 51.142,58.694 53.264,58.694 58.489,63.92 58.489,73.679 56.907,75.261 56.907,90.307 58.489,91.89 58.489,136.697 56.445,138.742 56.445,147.32 76.325,167.2 88.767,167.2 J3D.8@93.567,172
eQEP_BE: C7A.1 J3E.8 R5A.1 U46A.11 | length 122.7
  Top Layer w0.254: v2(46,162) 46,130.755 47.419,129.336 v2(47.419,104.906) ; R5A.1@46.971,67.058 R5A.1@47.065,67.151 ; R5A.1@47.065,66.951 47.065,67.058 R5A.1@47.065,67.151 ; v2(50.645,70.251) 50.528,70.134 49.919,70.134 49.453,69.668 49.453,67.926 49.043,67.516 48.881,67.516 C7A.1@48.608,67.243 ; U46A.11@56.763,66.44 52.928,66.44 52.898,66.41 49.392,66.41 C7A.1@48.608,67.193 ; R5A.1@47.065,67.151 48.517,67.151 C7A.1@48.608,67.243 ; C7A.1@48.608,67.193 C7A.1@48.608,67.243 ; C7A.1@48.608,67.193 C7A.1@48.608,67.243
  Mid-Layer 1 w0.254: v2(46,162) 46.046,162 56.046,172 J3E.8@56.091,172 ; v2(47.419,104.906) 48,104.325 48,72.895 v2(50.645,70.251)
eQEP_BF: C7B.1 J3F.8 R5B.1 U46B.11 | length 116.4
  Top Layer w0.254: U46B.11@8.546,81.656 8.546,84.753 8.516,84.783 8.516,87.589 8.879,87.952 9.024,87.952 9.387,88.314 ; C7B.1@9.293,91.685 9.293,90.249 9.387,90.155 9.387,88.314 ; v2(13,89) 10.072,89 9.387,88.314
  Mid-Layer 1 w0.254: v2(13,89) 13,97.423 9.524,100.899 3,100.899 2.025,101.873 2.025,161.799 6.226,166 12.615,166 J3F.8@18.615,172
eQEP_IA: C5B.1 J3A.9 R3B.1 U46B.13 | length 125.7
  Top Layer w0.254: v2(6.684,97.115) 6.684,95.215 6.684,93.685 6.774,93.595 6.774,93.028 7.546,92.255 U46B.13@7.546,81.656
  Mid-Layer 1 w0.254: v2(6.684,97.115) 6.8,96.998 7.146,96.998 9.546,94.598 9.546,63.534 13.043,60.037 22.166,60.037 25.446,56.756 25.446,20.124 38.334,7.235 39.561,7.235 J3A.9@39.615,7.181
eQEP_ID: C5A.1 J3D.9 R3A.1 U46A.13 | length 166.7
  Top Layer w0.254: v4(41.6,63.901) 41.642,63.901 42.196,64.455 43.211,64.455 R3A.1@43.335,64.578 ; R3A.1@43.335,64.778 R3A.1@43.335,64.578 ; C5A.1@44.865,64.628 C5A.1@44.865,64.578 ; U46A.13@56.763,65.44 46.504,65.44 45.642,64.578 C5A.1@44.865,64.578 ; R3A.1@43.335,64.578 C5A.1@44.865,64.578
  Mid-Layer 2 w0.254: v4(41.6,63.901) 43.744,61.757 43.744,61.176 45.772,59.148 53.039,59.148 57.452,63.562 57.452,74.073 56.453,75.073 56.453,90.495 57.452,91.495 57.452,106.917 56.767,107.603 56.335,107.603 55.997,107.941 55.997,108.373 55.512,108.857 55.512,147.733 75.783,168.003 86.07,168.003 J3D.9@90.067,172
eQEP_IE: C16A.1 J3E.9 R6A.1 U46A.10 | length 117.7
  Top Layer w0.254: v2(44.865,160) 44.865,159.835 45.341,159.359 45.341,105.356 45.736,104.961 v2(45.736,104.796) ; v2(50.369,67.967) 50.486,67.85 50.929,67.85 51.166,67.614 51.166,67.557 C16A.1@51.586,67.137 51.649,67.2 53.855,67.2 53.977,67.2 R6A.1@54.168,67.391 ; R6A.1@53.855,67.078 53.992,66.94 U46A.10@56.763,66.94
  Mid-Layer 1 w0.254: v2(44.865,160) 44.865,163.865 52.591,171.591 J3E.9@52.591,172 ; v2(45.736,104.796) 45.786,104.746 45.786,82.044 44.64,80.897 44.64,75.125 50.369,69.396 v2(50.369,67.967)
eQEP_IF: C16B.1 J3F.9 R6B.1 U46B.10 | length 114
  Top Layer w0.254: U46B.10@9.046,81.656 9.046,83.178 9.315,83.447 9.315,84.647 9.638,84.97 R6B.1@9.671,84.97 ; C16B.1@9.243,87.053 9.306,86.991 9.306,85.293 9.629,84.97 R6B.1@9.671,84.97 ; v2(12,83.632) 10.451,83.632 9.823,84.259 9.823,84.818 R6B.1@9.671,84.97
  Mid-Layer 1 w0.254: v2(12,83.632) 10.846,84.786 10.846,98.418 9.464,99.799 2.518,99.799 1.286,101.031 1.286,162.106 6.18,167 10.115,167 J3F.9@15.115,172
GND: C1A.2 C1B.2 C2A.2 C2B.2 C3A.2 C3B.2 C4A.2 C4B.2 C5A.2 C5B.2 C6A.2 C6B.2 C7A.2 C7B.2 C8A.2 C8B.2 C8C.2 C8D.2 C8E.2 C9A.2 C9B.2 C9C.2 C9D.2 C9E.2 C10A.2 C10B.2 C10C.2 C10D.2 C10E.2 C11A.2 C11B.2 C11C.2 C11D.2 C11E.2 C16A.2 C16B.2 C18A.2 C18B.2 C22A.2 C22B.2 C24A.2 C24B.2 C25A.2 C25B.2 C26A.2 C26B.2 C30A.2 C30B.2 C32.2 C33.2 C36.2 C37.2 C46A.1 C46B.1 C50A.1 C50B.1 C51A.1 C51B.1 C59A.2 C59B.2 C60A.1 C60B.1 C113A.2 C113B.2 C114A.2 C114B.2 C116A.2 C116B.2 C120A.2 C120B.2 D8A.1 D8B.1 D9A.2 D9B.2 J1.22 J2.20 J5.62 J6.60 J12.5 J15.1 J17.1 J21.5 NT10.1 NT10A.1 NT10B.1 NT11.1 Q3A.2@20.111,96.607 Q3B.2@84.604,97.436 R7A.1 R7B.1 R13A.1 R13B.1 R20A.1 R20B.1 R20C.1 R20D.1 R20E.1 R26A.1 R26B.1 R29.1 R39A.1 R39B.1 R43A.1 R43B.1 R45A.1 R45B.1 R48A.1 R48B.1 R143A.1 R143B.1 R145A.1 R145B.1 TP6.1 TP20A.1 TP20B.1 TP20C.1 TP20D.1 TP20E.1 TP29A.1 TP29B.1 U2.4 U3.5 U4A.5 U4B.5 U4C.5 U4D.5 U4E.5 U5A.5 U5B.5 U5C.5 U5D.5 U5E.5 U6A.2 U6A.6 U6B.2 U6B.6 U8A.8 U8B.8 U9.5 U10A.4 U10B.4 U10C.4 U10D.4 U10E.4 U11A.4 U11A.11 U11B.4 U11B.11 U14A.10 U14A.15 U14B.10 U14B.15 U46A.9 U46A.17 U46B.9 U46B.17 | length 36.8
  Top Layer w0.2: v6(4.361,89.265) 4.361,89.376 4.084,89.652 4.084,90.6 4.384,90.9 4.384,90.965 4.834,91.415 4.834,91.419 5.02,91.605 5.02,92.704 5.284,92.968 C5B.2@5.284,93.685 ; C7B.2@10.693,91.685 10.737,91.64 v6(11.846,91.64) ; v6(38.373,100.119) 38.452,100.041 38.628,100.041 39.389,99.28 R48A.1@39.389,99.255 ; C26A.2@41.439,91.189 41.464,91.189 42.252,91.977 42.252,93.749 C30A.2@41.954,94.048 41.954,94.073 42.606,94.725 U8A.8@42.606,95.434 ; C5A.2@44.865,63.178 45.582,63.178 45.846,62.914 47.201,62.914 47.901,62.214 C4A.2@47.926,62.214 ; C24A.2@45.261,97.484 45.261,99.235 45.621,99.595 45.621,100.917 46.209,101.505 51.281,101.505 v4(52.682,102.905) ; C26B.2@105.933,92.017 105.958,92.017 106.745,92.805 106.745,93.959 106.485,94.219 106.485,94.838 C30B.2@106.448,94.876 106.448,94.901 107.1,95.553 U8B.8@107.1,96.262
  Top Layer w0.254: v3(66.983,105.697) 66.983,105.63 67.203,105.41 U14A.10@67.203,104.347 ; v4(109.495,99.668) 109.495,98.572 C24B.2@109.755,98.312 ; v3(122.029,110.024) 122.029,109.958 122.249,109.738 U14B.10@122.249,108.674
  other v3: 67.983,105.697 68.983,105.697 65.983,106.697 66.983,106.697 67.983,106.697 68.983,106.697 69.983,106.697 66.983,107.697 67.983,107.697 68.983,107.697 54.174,108.18 55.374,108.18 56.574,108.18 123.029,110.024 124.029,110.024 121.029,111.024 122.029,111.024 123.029,111.024 124.029,111.024 125.029,111.024 122.029,112.024 123.029,112.024 124.029,112.024 109.22,112.507 110.42,112.507 111.62,112.507
  other v4: 47.626,70.542
  other v6: 49.218,61.267 12.09,87.612 102.7,100.324 57.826,111.96 108.304,116.399
GND_ENC: C20A.2 C20B.2 C28A.2 C28B.2 C29A.2 C29B.2 C31A.2 C31B.2 L2A.1 L2B.1 L2C.1 L2D.1 L2E.1 L4.1 NT10A.2 NT10B.2 TP38A.1 TP38B.1 TP39A.1 TP39B.1 | length 85.7
  Top Layer w0.254: C31A.2@20.193,103.429 20.193,103.454 20.466,103.727 22.957,103.727 TP38A.1@22.976,103.746 ; C31B.2@84.543,103.879 86.293,103.879 86.988,104.575 TP38B.1@87.469,104.575 ; NT10B.2@117,73.88 NT10B.2@117.105,73.775
  Top Layer w0.508: NT10B.2@117,73.88 TP39B.1@117,77.364
  Top Layer w1.27: C20A.2@20.757,77.171 C29A.2@32.464,77.171 ; C29A.2@32.787,77.171 C28A.2@44.217,77.171 50.958,77.171 51.594,76.535 TP39A.1@51.8,76.535 ; v7(46.757,75.321) 48.733,73.346 NT10A.2@52.092,73.346 ; C20B.2@85.205,78 C29B.2@96.958,78 ; C29B.2@97.281,78 C28B.2@108.711,78 111.079,78 116.158,78 116.794,77.364 TP39B.1@117,77.364
  Bottom Layer w0.635: v5@20.189,147.575 20.756,147.575 20.773,147.592 v5@21.349,147.592 ; v5@26.593,25.056 27.18,25.056 27.192,25.068 v5@27.761,25.068 ; v5@63.491,147.371 64.067,147.371 64.099,147.403 v5@64.666,147.403 ; v5@69.462,23.857 69.469,23.851 70.639,23.851 v5@70.642,23.848 ; v5@108.185,149.607 108.185,149.049 108.233,149.001 v5@108.233,148.435 ; v5@110.634,25.207 111.219,25.207 111.236,25.224 v5@111.814,25.224
  other v5: 69.45,23.686 70.049,23.686 70.662,23.686 26.581,24.848 27.18,24.848 27.793,24.848 110.635,25.016 111.234,25.016 111.848,25.016 63.453,147.194 64.052,147.194 64.665,147.194 20.163,147.393 20.762,147.393 21.376,147.393 108.374,148.444 108.374,149.043 108.374,149.657
  other v7: 23.012,75.187 35.111,77.056 29.924,77.119 41.69,77.114 87.88,78 94.283,78 99.897,78 106.249,78 111.079,78.1 82.625,78.624 23.192,78.944
GND_EXT: J3A.10 J3B.10 J3C.10 J3D.10 J3E.10 J3F.10 J13.2 J14.2 J19.2 J20.2 NT10.2 NT11.2 | length 10.6
  Top Layer w0.54: J14.2@128.86,162.623 J14.2@128.733,162.75 131.414,160.069 NT10.2@131.414,155.595 131.38,155.629 130.215,155.629 130.19,155.654 129.285,155.654 NT11.2@129.271,155.668
LP_3V3: C1A.1 C1B.1 J1.1 J5.41 J15.3 J17.3 J18.4 R8A.2 R8B.2 R8C.2 R8D.2 R8E.2 R9A.2 R9B.2 R9C.2 R9D.2 R9E.2 R16A.1 R16B.1 R16C.1 R16D.1 R16E.1 R18A.1 R18B.1 R18C.1 R18D.1 R18E.1 U5A.2 U5B.2 U5C.2 U5D.2 U5E.2 U10A.8 U10B.8 U10C.8 U10D.8 U10E.8 U46A.2 U46B.2 | length 480
  Top Layer w0.254: C1B.1@3.55,78.059 5.105,78.059 5.252,78.206 U46B.2@6.546,78.206 ; v1(19.023,55.276) 19.731,54.568 U10D.8@19.731,54.166 20.245,54.166 ; 27.871,124.514 27.871,124.552 27.99,124.672 U10C.8@28.227,124.672 ; U46A.2@60.213,64.44 60.397,64.44 60.409,64.428 60.409,63.793 60.491,63.711 60.491,62.304 ; 70.202,123.375 70.202,123.409 ; U10B.8@71.278,124.485 U10B.8@71.528,124.485 71.691,124.485 71.712,124.463 71.712,123.899 v1(72.236,123.375) ; v1(103.065,55.438) 103.773,54.73 U10E.8@103.773,54.328 ; 113.872,124.512 113.872,124.554 113.99,124.672 U10A.8@114.227,124.672
  Top Layer w0.381: C1B.1@3.55,78.059 3.759,77.849 3.759,77.359 4.116,77.002 v6(4.116,76.941) ; U5D.2@6.024,41.985 7.637,41.985 7.657,42.005 ; R9D.2@7.424,37.775 7.283,37.916 7.283,39.841 7.657,40.215 7.657,42.005 ; v1(8.498,48.258) 7.657,47.417 7.657,42.005 ; R16C.1@20.169,130.782 20.169,128.456 R8C.2@20.444,128.181 20.444,126.525 22.298,124.672 27.713,124.672 27.871,124.514 28.823,123.562 v1(28.935,123.562) ; 20.245,54.166 24.52,54.166 26.278,52.408 R8D.2@26.278,50.033 ; R16D.1@27.789,48.056 27.789,49.468 27.249,50.008 R8D.2@26.278,50.008 R8D.2@26.278,50.033 ; v1(39.46,130.58) 40.301,131.421 40.301,135.645 ; R9C.2@40.534,141.062 40.675,140.921 40.675,138.997 40.301,138.623 40.301,135.645 ; U5C.2@41.934,136.852 41.509,136.852 40.301,135.645 ; v6(45.725,52.2) 28.47,52.2 26.512,50.242 26.487,50.242 R8D.2@26.278,50.033 ; C1A.1@60.491,61.444 60.506,61.459 60.506,62.304 60.617,62.416 60.729,62.528 61.938,62.528 v6(61.952,62.513) ; v6(62.582,126.502) 62.625,126.458 63.455,126.458 63.481,126.431 ; R16B.1@63.47,130.595 63.47,127.764 R8B.2@63.481,127.753 63.481,126.431 ; v1(72.236,123.375) 70.202,123.375 66.538,123.375 63.481,126.431 ; v1(82.761,130.392) 83.602,131.233 83.602,135.458 ; R9B.2@83.834,140.875 83.975,140.734 83.975,138.81 83.602,138.436 83.602,135.458 ; U5B.2@85.234,136.665 84.809,136.665 83.602,135.458 ; U5E.2@90.066,42.148 91.656,42.148 91.699,42.191 ; R9E.2@91.466,37.938 91.325,38.079 91.325,40.003 91.699,40.377 91.699,42.191 ; v1(92.54,48.42) 91.699,47.579 91.699,42.191 ; v6(93.101,127.592) 94.292,128.783 105.817,128.783 106.002,128.598 106.04,128.598 106.25,128.389 R8A.2@106.25,128.364 106.169,128.445 R16A.1@106.169,130.782 ; v1(103.065,55.438) 107.946,55.438 110.065,53.319 110.065,52.863 R8E.2@110.273,52.655 110.319,52.702 110.85,52.702 111.831,51.721 R16E.1@111.831,48.218 ; R8A.2@106.25,128.339 109.917,124.672 113.713,124.672 113.872,124.512 114.823,123.562 v1(114.935,123.562) ; v1(125.46,130.58) 126.301,131.421 126.301,135.645 ; R9A.2@126.534,141.062 126.675,140.921 126.675,138.997 126.301,138.623 126.301,135.645 ; U5A.2@127.934,136.852 127.509,136.852 126.301,135.645
  Mid-Layer 1 w0.381: v1(8.498,48.258) 10.421,48.258 15.17,53.007 15.17,54.516 15.93,55.276 v1(19.023,55.276) ; v1(28.935,123.562) 32.028,123.562 32.788,124.322 32.788,125.831 37.537,130.58 v1(39.46,130.58) ; v1(72.236,123.375) 75.328,123.375 76.088,124.135 76.088,125.644 80.837,130.392 v1(82.761,130.392) ; v1(92.54,48.42) 94.463,48.42 99.212,53.169 99.212,54.678 99.972,55.438 v1(103.065,55.438) ; v1(114.935,123.562) 118.028,123.562 118.788,124.322 118.788,125.831 123.537,130.58 v1(125.46,130.58)
  Mid-Layer 2 w0.381: v6(4.116,76.941) 4.081,76.906 4.081,75.868 13.562,66.387 J1.1@16.337,66.387 ; J5.41@79.837,66.387 92.54,53.684 v1(92.54,48.42)
  Bottom Layer w0.381: J1.1@16.337,66.387 16.337,61.892 19.023,59.206 v1(19.023,55.276) ; v1(39.46,130.58) 41.685,128.355 60.728,128.355 v6(62.582,126.502) 62.582,85.529 66.049,82.062 66.049,81.161 66.004,81.116 66.004,74.02 70.338,69.685 J15.3@70.338,66.486 ; v6(45.725,52.2) 52.158,58.633 55.112,58.633 55.857,59.378 58.817,59.378 v6(61.952,62.513) 63.559,62.513 67.532,66.486 J15.3@70.338,66.486 ; J5.41@79.837,66.387 79.787,66.436 70.387,66.436 J15.3@70.338,66.486 ; v1(82.761,130.392) 85.561,127.592 v6(93.101,127.592) ; J17.3@107.398,67.283 103.065,62.95 v1(103.065,55.438) 118.208,55.438 J18.4@121.226,52.42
